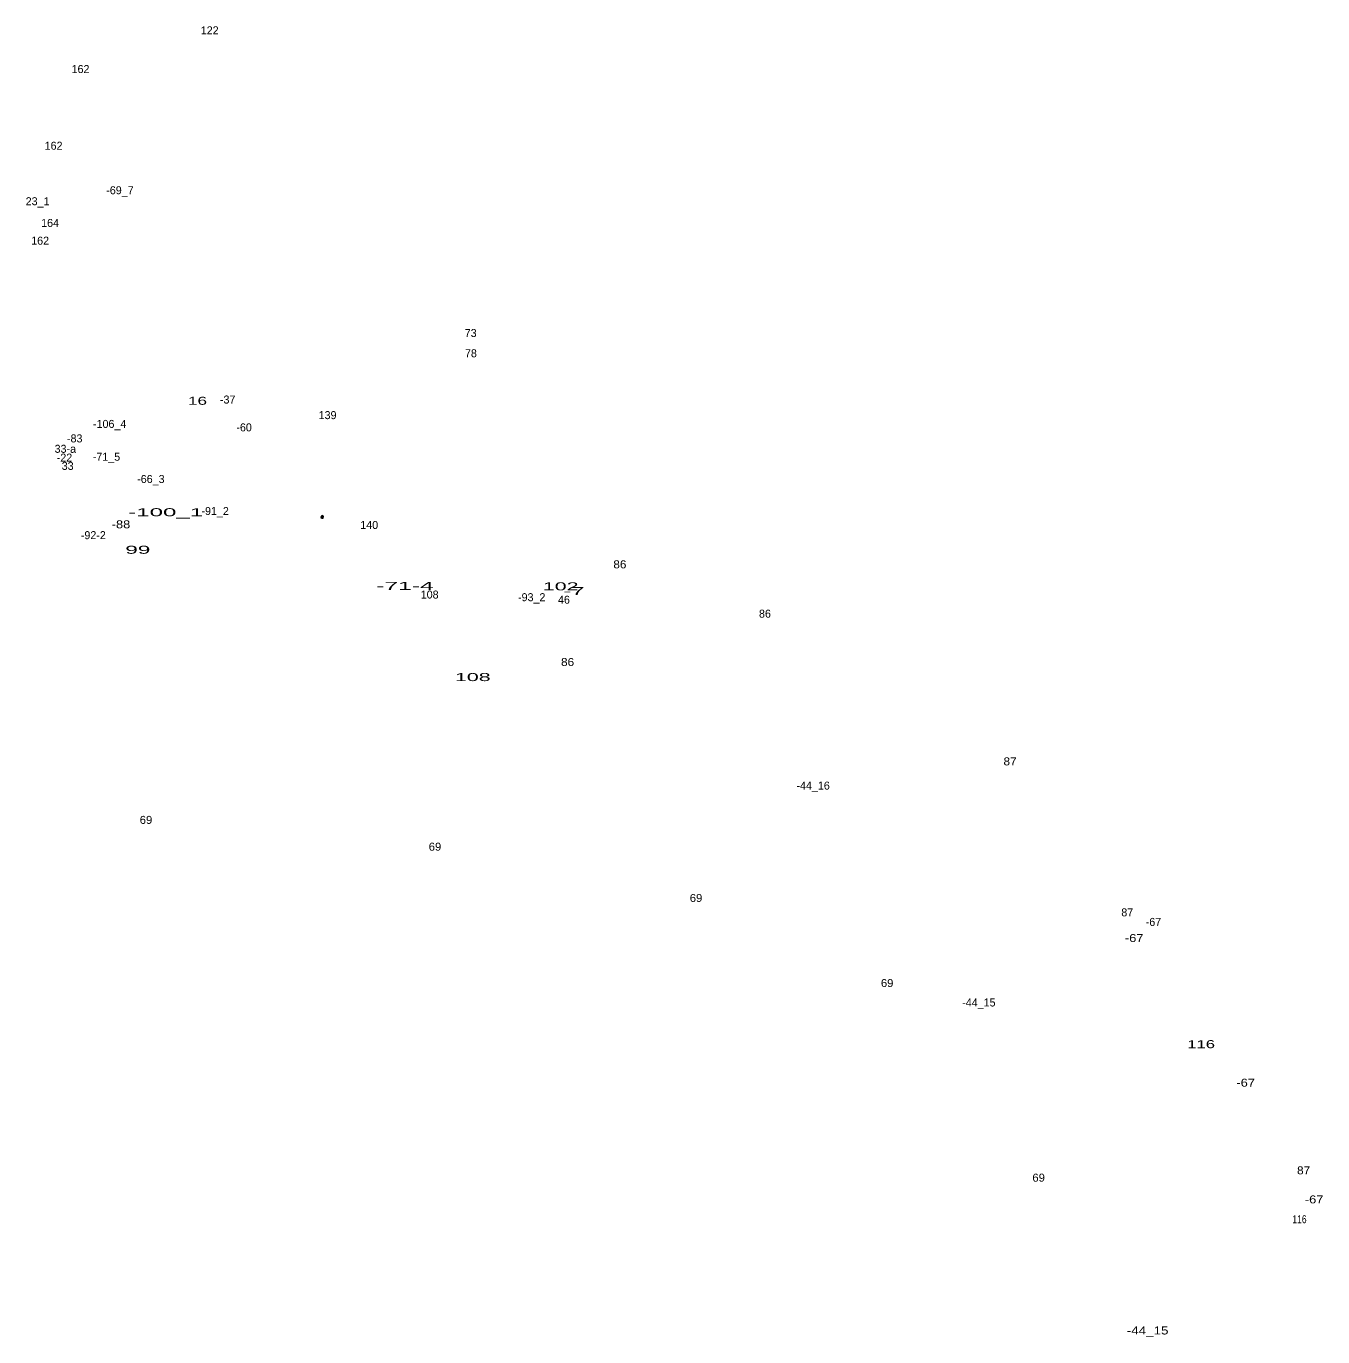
# Model space of a CAD drawing. Extents: x -665231 to -661652, y -987317 to -984562.
# Drawn here: x -662886 to -662238, y -986362 to -985707 of the extents above; entities that cross this region are included whole.
import ezdxf
from ezdxf.enums import TextEntityAlignment as Align

# ---------------------------------------------------------------- set-up
doc = ezdxf.new("R2010")
doc.units = 0
doc.header["$LTSCALE"] = 1.6
doc.layers.add('24', color=7, linetype='Continuous', lineweight=25)

msp = doc.modelspace()

# ---------------------------------------------------------------- linework, layer by layer
at = {"layer": '24'}
for radius in [0.5, 0.0364]:
    msp.add_circle((-662738, -985952.31), radius, dxfattribs=at)
msp.add_arc((-662738.003, -985951.936), 0.45, 344.44728, 196.37785, dxfattribs=at)

# ---------------------------------------------------------------- texts
for s, p in [('122', (-662794.27, -985710.841)), ('162', (-662858.812, -985730.205)), ('162', (-662872.272, -985768.53)), ('-69_7', (-662839.119, -985790.808)), ('23_1', (-662880.272, -985796.287)), ('164', (-662874.018, -985807.145)), ('162', (-662879.002, -985816.005)), ('73', (-662663.835, -985862.169)), ('78', (-662663.715, -985872.296)), ('-37', (-662785.282, -985895.438)), ('139', (-662735.351, -985903.227)), ('-106_4', (-662844.245, -985907.622)), ('-60', (-662777.069, -985909.349)), ('-83', (-662861.721, -985914.873)), ('33-a', (-662866.415, -985920.061)), ('-22', (-662866.845, -985924.459)), ('-71_5', (-662845.852, -985924.036)), ('33', (-662865.229, -985928.603)), ('-66_3', (-662823.653, -985935.163)), ('-91_2', (-662791.534, -985951.174)), ('-92-2', (-662852.417, -985963.24)), ('140', (-662714.54, -985958.147)), ('108', (-662684.328, -985992.936)), ('-93_2', (-662633.319, -985994.265)), ('46', (-662617.227, -985995.517)), ('86', (-662516.776, -986002.492)), ('-44_16', (-662492.699, -986088.467)), ('87', (-662335.7, -986151.828)), ('-67', (-662322.611, -986156.619)), ('-44_15', (-662409.847, -986196.872))]:
    msp.add_text(s, height=4, dxfattribs=at).set_placement(p, align=Align.CENTER)
for s, width, p in [('16', 1.6, (-662800.352, -985896.056)), ('-100_1', 2.25, (-662816.249, -985951.783)), ('-88', 1.2, (-662838.586, -985957.814)), ('99', 2.1, (-662830.191, -985970.542)), ('86', 1.1, (-662589.265, -985977.827)), ('-71-4', 2.3, (-662696.689, -985988.585)), ('102', 2, (-662618.859, -985988.832)), ('-7', 2.2, (-662612.243, -985991.214)), ('86', 1.1, (-662615.399, -986026.664)), ('108', 2, (-662662.788, -986034.195)), ('87', 1.1, (-662394.272, -986076.353)), ('69', 1.05, (-662826.099, -986105.6)), ('69', 1.05, (-662681.666, -986119.001)), ('69', 1.05, (-662551.211, -986144.637)), ('-67', 1.2, (-662332.242, -986164.657)), ('69', 1.05, (-662455.701, -986187.168)), ('116', 1.55, (-662298.769, -986217.729)), ('-67', 1.2, (-662276.52, -986236.997)), ('69', 1.05, (-662379.99, -986284.469)), ('87', 1.1, (-662247.575, -986280.826)), ('-67', 1.2, (-662242.309, -986295.335)), ('116', 0.8, (-662249.647, -986305.255)), ('-44_15', 1.25, (-662325.513, -986360.875))]:
    msp.add_text(s, height=4, dxfattribs=dict(at, width=width)).set_placement(p, align=Align.CENTER)

doc.saveas('drawing.dxf')
